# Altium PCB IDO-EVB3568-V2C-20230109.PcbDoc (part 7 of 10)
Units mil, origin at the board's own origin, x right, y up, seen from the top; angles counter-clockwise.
Board outline 5318 x 3544 mil, 2 copper layers (TOP, BOTTOM), stack 6.8 mil thick; 790 components, 626 nets, 2890 pads, 1922 vias.
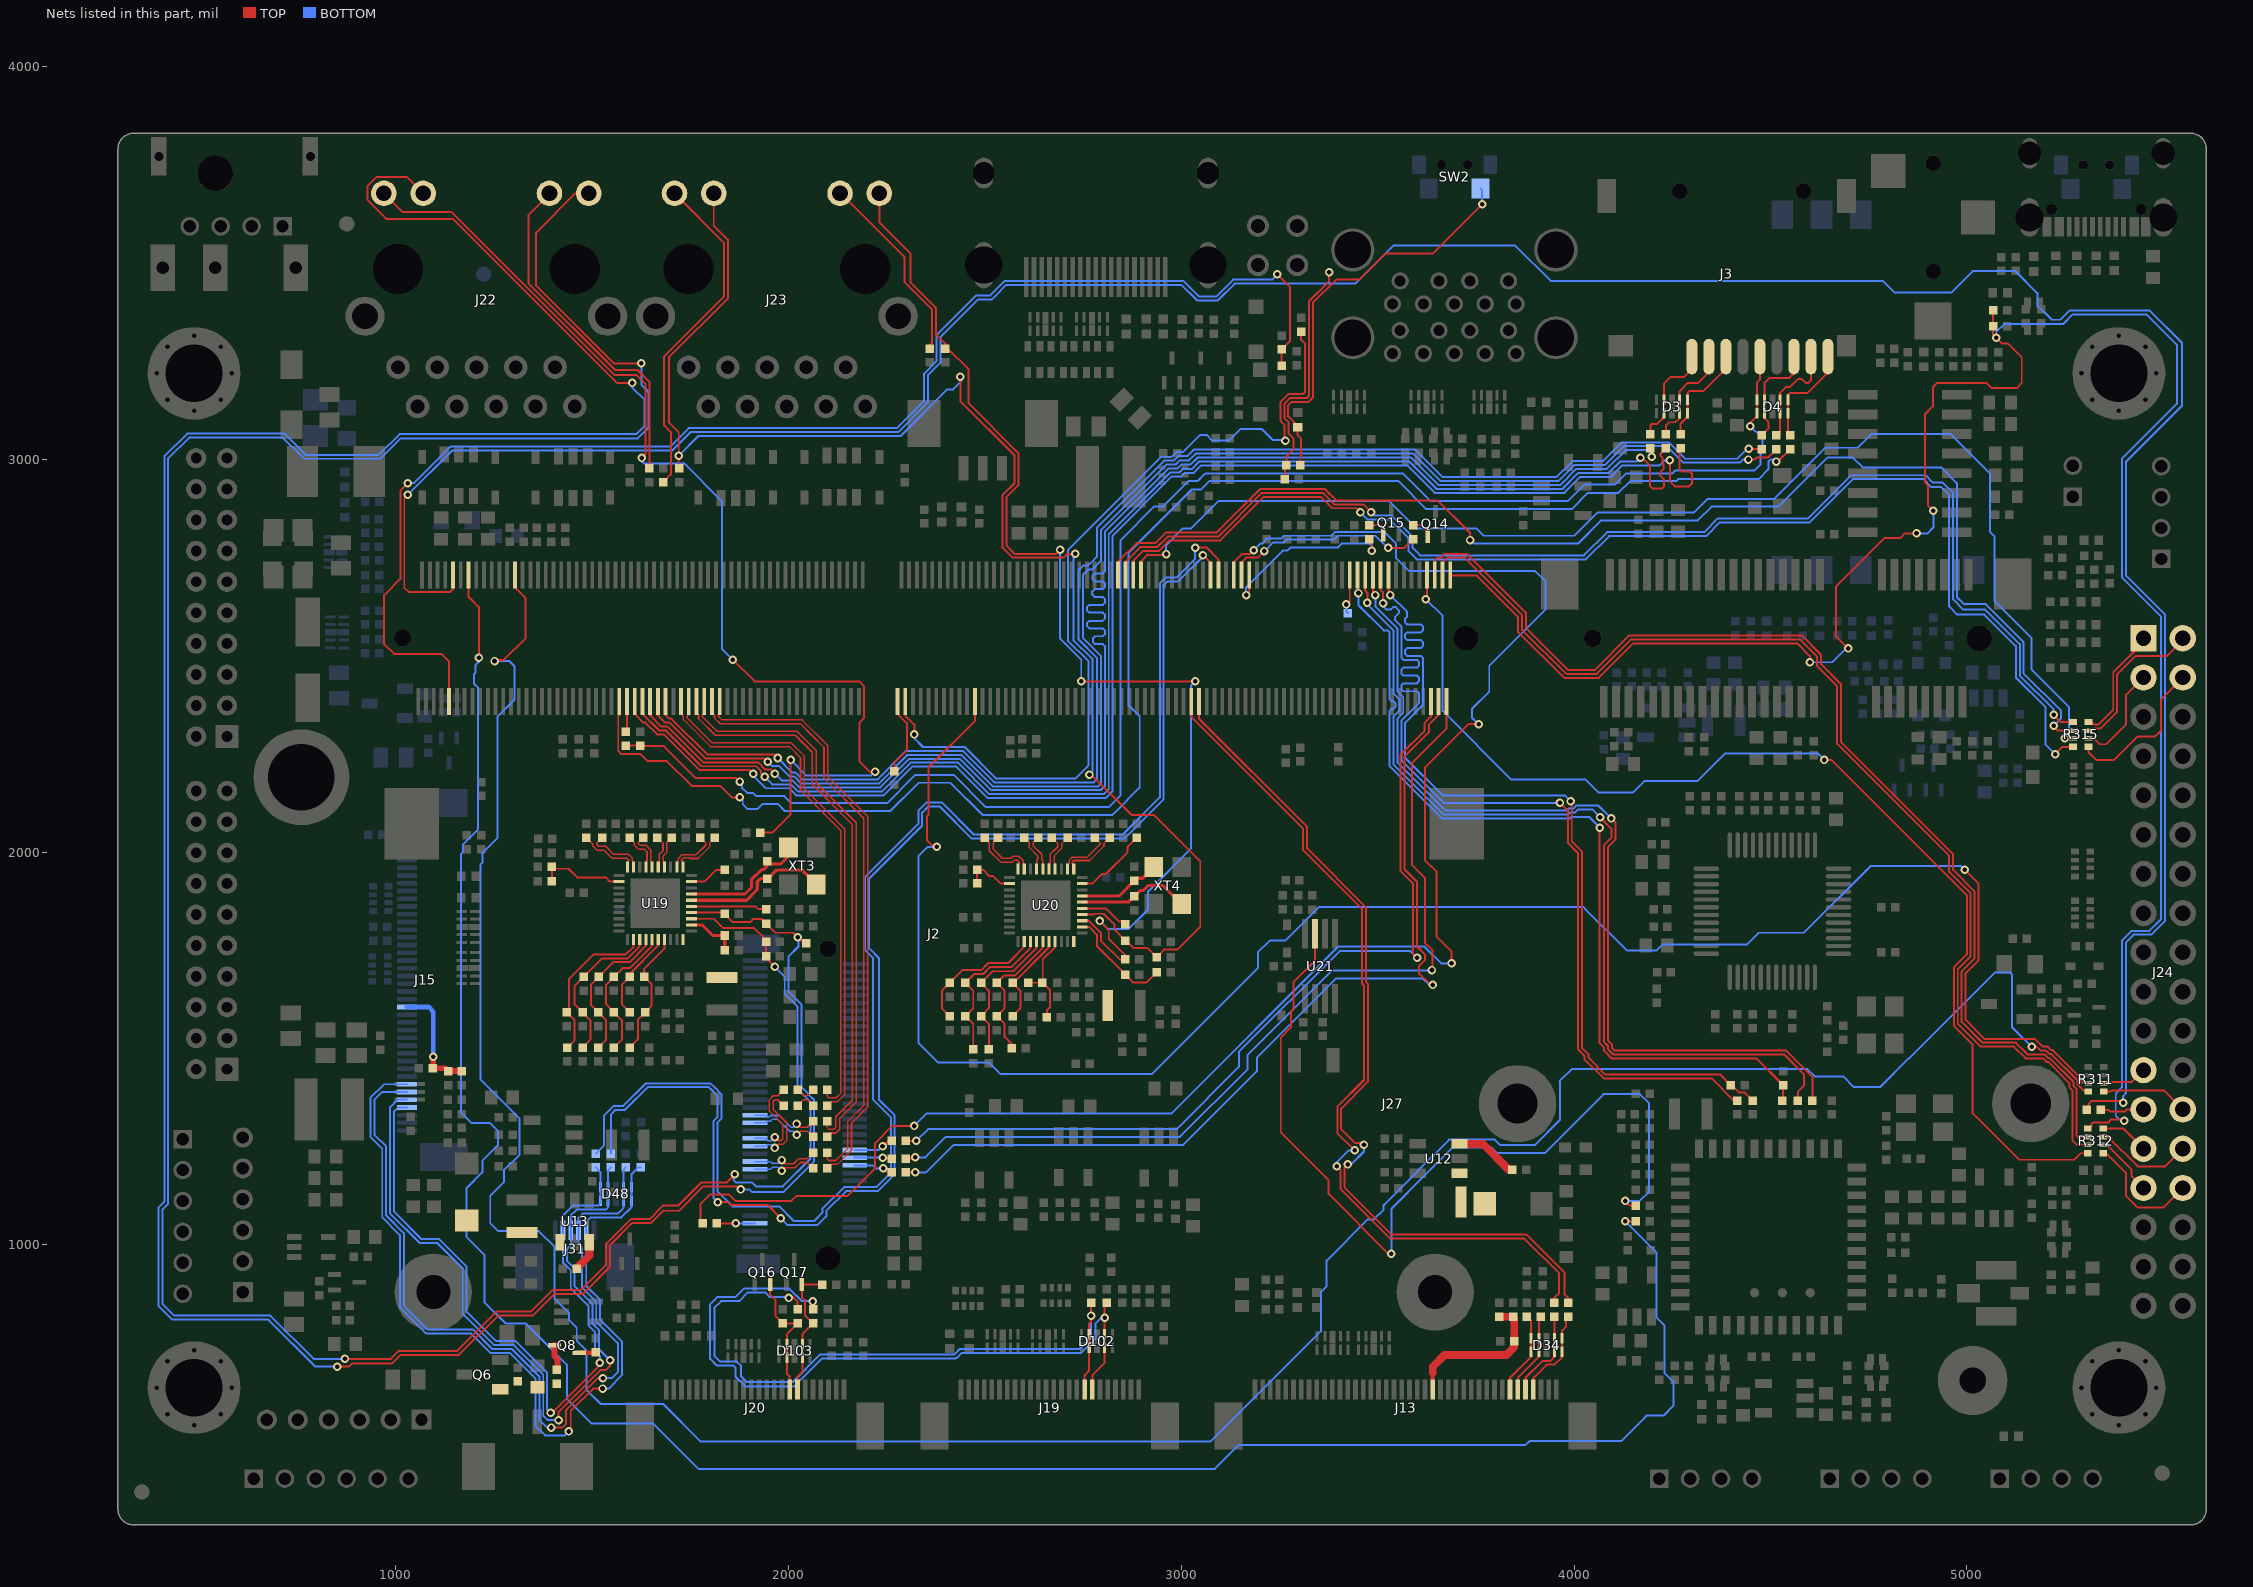
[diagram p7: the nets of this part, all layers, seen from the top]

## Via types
v1: diameter 21.65, hole 11.81, TOP to BOTTOM, 1878 vias
v2: diameter 17.72, hole 7.87, TOP to BOTTOM, 44 vias

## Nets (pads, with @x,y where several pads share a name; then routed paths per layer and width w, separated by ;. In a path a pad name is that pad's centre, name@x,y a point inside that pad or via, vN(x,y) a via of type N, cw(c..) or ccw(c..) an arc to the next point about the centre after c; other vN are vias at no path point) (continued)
N69911722: R99.2 U12.3 | length 161.6
  TOP w20: U12.3@3708.15,1257.4 3767.6,1257.4 3834,1191 R99.2@3842.28,1191
N69911786: C78.2 J13.17 R413.2 R415.2 | length 399.8
  TOP w10: J13.17@3639.96,632.01 3639.96,675
  TOP w20: 3639.96,675 3639.96,689.96 3670,720 3827.72,720 3847.72,740 C78.2@3847.72,755 3847.72,814.56 R413.2@3845,817.28 R415.2@3810,817.28
N69912226: D39.A L15.2 U12.1
N69922645: R117.2 U13.3 | length 80.4
  TOP w20: R117.2@1459.72,940 1492.4,972.68 U13.3@1492.4,1006.85
N69922778: D50.A L20.2 U13.1
N69927169: C92.1 Q6.1 R134.1 R136.1
N69927197: Q8.3 R136.2 | length 67.2
  TOP w15: Q8.3@1403.5,745 1403.5,716.5 1411,709 1411,683.72 R136.2@1409,681.72
N69927388: Q8.1 R137.1 | length 43.3
  TOP w12: Q8.1@1466.5,725.32 1507.04,725.32 R137.1@1509,727.28
N70033042: Q15.1 R89.2 | length 58.6
  TOP w5: R89.2@3478,2832.72 3509.32,2832.72 3514.32,2827.72 Q15.1@3514.32,2807.5
N70033056: Q14.1 R90.2 | length 56.1
  TOP w5: R90.2@3590,2832.72 3611.28,2832.72 3627.32,2816.68 Q14.1@3627.32,2804.5
N70059784: C258.2 J15.17 R408.2 R409.2 | length 293.9
  TOP w15: v1(1095,1479) 1095,1451.28 C258.2@1093.72,1450 1125.72,1450 R409.2@1133,1442.72 R408.2@1168,1442.72
  BOTTOM w12: J15.17@1027.99,1606.1 1083,1606.1 1095,1594.1 v1(1095,1479)
N70064377: D96.1 R412.2 SW2.3 | length 1056.2
  TOP w5: R412.2@3302.72,2985 3302.72,3004.33 3305,3006.61 3305,3053.38 3296,3062.38 D96.1@3296,3082.1 3296,3085.87 3272,3109.87 3272,3137.7 3281.3,3147 3324,3147 3335,3158 3335,3398.86 3395.14,3459 3454,3459 3520,3525 3640.95,3525 v1(3765.95,3650)
  BOTTOM w5: SW2.3@3761.95,3689.98 3765.95,3685.98 v1(3765.95,3650)
NTC_SARADC_VIN3: J2.5 R312.2 | length 2857.6
  TOP w5: J2.5@3645.27,2706.42 3645.27,2744 3650.27,2749 3660,2749 3671,2760 3727,2760 3877,2610 3877,2572 3985,2464 4053,2464 4141,2552 4579.25,2552 4629,2502.25 4629,2478.14 4680,2427.14 4680,2280.14 4965,1995.14 4965,1955 5020,1900 5020,1730 4987,1697 4987,1568 5040,1515 5125,1515 5155,1485 5198.09,1485 5207.16,1475.92 5211.02,1475.92 5271.97,1414.98 5271.97,1404.89 5278.92,1397.94 5278.92,1279.84 5283.92,1274.84 R312.2@5308.31,1274.84
PCIE20_CLKREQN_3V3_L: J27.52 R348.2 | length 95.3
  TOP w5: v1(2239.2,1222.2) 2241.41,1220 R348.2@2262.28,1220
  BOTTOM w5: J27.52@2167.91,1222.2 v1(2239.2,1222.2)
PCIE20_CLKREQN_M2_3V3_L: J2.2 R348.1 | length 2302.6
  TOP w5: R348.1@2297.72,1220 2319,1220 v1(2322,1223) ; v1(3638,1700) 3640,1702 3640,1750 3620,1770 3620,1935 3587.63,1967.37 3587.63,2227.63 3674.8,2314.8 J2.2@3674.8,2383.58
  BOTTOM w5: v1(2322,1223) 2348,1223 2400,1275 2412.14,1275 2445.28,1275.01 2467.86,1275 2996.29,1275 3168,1446.71 3168,1483 3384,1699 3637,1699 v1(3638,1700)
PCIE20_PERSTN_3V3_L: J27.50 R347.2 | length 103.9
  TOP w5: v1(2239,1250.89) 2253.11,1265 R347.2@2262.28,1265
  BOTTOM w5: J27.50@2167.91,1241.89 2230,1241.89 v1(2239,1250.89)
PCIE20_PERSTN_M2_3V3_L: J2.6 R347.1 | length 2234
  TOP w5: R347.1@2297.72,1265 v1(2325,1265) ; v1(3600,1731) 3590,1741 3590,1920 3557.63,1952.37 3557.63,2247.63 3618.5,2308.5 3618.5,2328.5 3635.43,2345.43 J2.6@3635.43,2383.58
  BOTTOM w5: v1(2325,1265) 2355,1295 2403.86,1295 2453.57,1295.01 ; 2453.57,1295 2476.14,1295 2988,1295 3146.5,1453.5 3146.5,1491.5 3403,1748 3583,1748 v1(3600,1731)
PCIE20_PRSNT_3V3_L: J27.69 R382.1 | length 97.3
  TOP w5: R382.1@1816.72,1055 1816.84,1054.88 v1(1865.12,1054.88)
  BOTTOM w5: v1(1865.12,1054.88) J27.69@1913.98,1054.88
PCIE20_PRSNT_3V3_L_GPIO3_A6: J2.57 R382.2 | length 4396
  TOP w5: R382.2@1781.28,1055 1780,1055 1775,1060 1775,1103.66 1800.34,1129 1847,1129 1864,1112 2007,1112 2020,1125 2150,1125 2220,1195 2220,1259.43 2263.57,1303 v1(2320,1303) ; J2.57@3133.46,2706.42 3133.46,2738.46 3155,2760 3175,2760 v1(3184,2769) ; v1(3688,1717) 3688,1747 3650,1785 3650,1950 3620,1980 3620,2215 3731,2326 v1(3757,2326)
  BOTTOM w5: v1(2320,1303) 2352,1335 2975,1335 3400,1760 3619,1760 3662,1717 v1(3688,1717) ; v1(3184,2769) 3201,2786 3206,2786 3219,2799 3254,2799 3261,2806 3382,2806 3392,2816 3517,2816 3547,2786 3547,2749 3580,2716 3901,2716 3927.33,2689.67 3927.33,2618.33 3784,2475 3784,2409 3740,2365 3740,2343 v1(3757,2326)
PCIE20_REFCLKN: J2.184 R360.1 | length 1517.3
  TOP w4: J2.184@1804.72,2383.58 1804.72,2355.28 1811,2349 1811,2342 1826,2327 2029.86,2327 2059.93,2296.93 2090,2266.86 2090,2187.86 2191,2086.86 2191,1355.14 2150,1314.14 2150,1245 2120,1215 2101.72,1215 2097.72,1219 R360.1@2097.72,1235
PCIE20_REFCLKN_: J27.53 R360.2 | length 169.3
  TOP w4: v1(1982,1216.16) 1991.16,1207 2012.86,1207 2025.86,1220 2047.28,1220 R360.2@2062.28,1235
  BOTTOM w4: J27.53@1913.98,1212.36 1953.47,1212.36 1958.31,1207.52 1973.35,1207.52 v1(1982,1216.16)
PCIE20_REFCLKP: J2.182 R361.1 | length 1519.2
  TOP w4: J2.182@1824.4,2383.58 1824.4,2353.84 1821,2350.44 1821,2346.14 1830.14,2337 2034,2337 2100,2271 2100,2192 2201,2091 2201,1351 2160,1310 2160,1240.86 2124.14,1205 2107.72,1205 R361.1@2097.72,1195
PCIE20_REFCLKP_: J27.55 R361.2 | length 168.9
  TOP w4: v1(1982,1188.87) 1990.13,1197 2017,1197 2030,1210 2047.28,1210 R361.2@2062.28,1195
  BOTTOM w4: J27.55@1913.98,1192.68 1953.47,1192.68 1958.31,1197.52 1973.36,1197.52 v1(1982,1188.87)
PCIE20_RXN: J2.188 R355.1 | length 1427.3
  TOP w4: J2.188@1765.35,2383.58 1765.35,2354.98 1770.33,2350 1770.33,2340.67 1813,2298 2016.86,2298 2059.93,2254.93 2059.93,2172.93 2162,2070.86 2162,1368.21 2120,1326.21 2120,1299 2116,1295 2101.72,1295 2097.72,1299 R355.1@2097.72,1315
PCIE20_RXN_: J27.41 R355.2 | length 178.2
  TOP w4: v1(2020,1308) 2028,1300 2047.28,1300 R355.2@2062.28,1315
  BOTTOM w4: J27.41@1913.98,1330.47 1939.53,1330.47 1945,1325 1948.86,1325 1953.49,1329.63 1976.37,1329.63 2006.67,1299.33 2011.33,1299.33 v1(2020,1308)
PCIE20_RXP: J2.186 R356.1 | length 1430.2
  TOP w4: J2.186@1785.03,2383.58 1785.03,2354.7 1780.33,2350 1780.33,2344.81 1817.14,2308 2021,2308 2069.93,2259.07 2069.93,2177.07 2172,2075 2172,1364.07 2130,1322.07 2130,1294.86 2120.14,1285 2107.72,1285 R356.1@2097.72,1275
PCIE20_RXP_: J27.43 R356.2 | length 178.4
  TOP w4: v1(2020.35,1280.35) 2030,1290 2047.28,1290 R356.2@2062.28,1275
  BOTTOM w4: J27.43@1913.98,1310.79 1940.79,1310.79 1945,1315 1953,1315 1957.63,1319.63 1972.23,1319.63 2002.53,1289.33 2011.38,1289.33 v1(2020.35,1280.35)
PCIE20_TX_N: C212.2 R357.1 | length 52
  TOP w4: R357.1@2022.72,1395 2037.72,1380 2047.28,1380 C212.2@2062.28,1395
PCIE20_TX_P: C213.2 R358.1 | length 52
  TOP w4: R358.1@2022.72,1355 2037.72,1370 2047.28,1370 C213.2@2062.28,1355
PCIE20_TXN: C212.1 J2.192 | length 1340.7
  TOP w4: J2.192@1725.98,2383.58 1725.98,2353.02 1732.01,2346.99 1732.01,2337.85 1800.86,2269 2001.86,2269 2030,2240.86 2030,2157.86 2133,2054.86 2133,1387.14 2120.86,1375 2101.72,1375 2097.72,1379 C212.1@2097.72,1395
PCIE20_TXN_: J27.47 R357.2 | length 242.9
  TOP w4: v1(1964.65,1274.22) 1972.87,1266 1981,1266 1985,1270 1985,1307 1951,1341 1951,1370.14 1960.86,1380 1972.28,1380 R357.2@1987.28,1395
  BOTTOM w4: J27.47@1913.98,1271.42 1940,1271.42 1945.84,1265.57 1956,1265.57 v1(1964.65,1274.22)
PCIE20_TXP: C213.1 J2.190 | length 1342.8
  TOP w4: J2.190@1745.66,2383.58 1745.66,2350.66 1742.01,2347.01 1742.01,2341.99 1805,2279 2006,2279 2040,2245 2040,2162 2143,2059 2143,1383 2125,1365 2107.72,1365 C213.1@2097.72,1355
PCIE20_TXP_: J27.49 R358.2 | length 242.4
  TOP w4: v1(1964.65,1246.93) 1973.72,1256 1985.14,1256 1995,1265.86 1995,1311.14 1961,1345.14 1961,1366 1965,1370 1972.28,1370 R358.2@1987.28,1355
  BOTTOM w4: J27.49@1913.98,1251.73 1940.16,1251.73 1944,1255.57 1956,1255.57 v1(1964.65,1246.93)
PCIE20_WAKEN_3V3_L: J27.54 R349.2 | length 101.6
  TOP w5: v1(2241,1195) 2251,1185 R349.2@2262.28,1185
  BOTTOM w5: J27.54@2167.91,1202.52 2214.15,1202.52 2221.67,1195 v1(2241,1195)
PCIE20_WAKEN_M2_3V3_L: J2.4 R349.1 | length 2377.6
  TOP w5: R349.1@2297.72,1185 v1(2322,1185) ; v1(3640,1662) 3635,1662 3605,1692 3605,1710 3620,1725 3620,1740 3600,1760 3600,1925 3567.63,1957.37 3567.63,2242.63 3630,2305 3630,2325 3655.11,2350.11 J2.4@3655.11,2383.58
  BOTTOM w5: v1(2322,1185) 2350,1185 2420,1255 2420.43,1255 2437,1255.01 2459.57,1255 2988,1255 3004.57,1255 3005,1255 3192,1442 3192,1477 3394,1679 3614,1679 3631,1662 v1(3640,1662)
PHY0_CLKOUT125: R216.2 U19.35 | length 192.7
  TOP w5: U19.35@1752.52,1862.13 1915,1862.13 1922.13,1855 R216.2@1942.28,1855
PHY0_G_LED-: J22.12 R213.1 | length 883.5
  TOP w5: J22.12@1390.8,3677.9 1390.8,3675.8 1337,3622 1337,3448.86 1557.86,3228 1615,3228 1645,3198 R213.1@1645,2977.72
PHY0_LED0/CFG_EXT: R225.2 R226.1 U19.32 | length 133.9
  TOP w8: U19.32@1752.52,1814.88 1780.12,1814.88 1807,1788 R225.2@1837.28,1788 R226.1@1837.28,1750
PHY0_LED1/CFG_LDO0: C133.2 J22.11 R233.2 U19.33 | length 7096.2
  TOP w5: v1(870,710) 987,710 1007,730 1155.86,730 1255.86,830 1343,830 1398,885 1470,885 1535,950 1535,994.86 1535,1003.14 1597.86,1066 1629.14,1066 1645.71,1066 1679.86,1100.14 1718.14,1100.14 1777,1159 1842,1159 v1(1863,1180) ; J22.11@1490.8,3677.9 1456.9,3677.9 1357,3578 1357,3443 1555,3245 v1(1625,3245) ; U19.33@1752.52,1830.63 1809.37,1830.63 1833,1807 1912,1807 1942.28,1776.72 C133.2@1942.28,1772 R233.2@1942.28,1735 1942.28,1730.72 v1(1965,1708)
  BOTTOM w5: v1(870,710) 790,710 680,820 435,820 405,850 405,1090 420,1105 420,3003 473,3056 712,3056 760.14,3007.86 766,3002 960.14,3002 1012.14,3054 1616,3054 1643,3081 1643,3172 1625,3190 v1(1625,3245) ; v1(1863,1180) 1860,1177 1860,1165 1865.41,1159.59 1906.16,1159.59 1916.75,1149 1985.14,1149 2055,1218.86 2055,1365 2023,1397 2023,1607 1990,1640 1990,1683 v1(1965,1708)
PHY0_LED2/CFG_LDO1: C132.2 J22.13 R229.2 R230.1 U19.34 | length 7598
  TOP w5: v1(850,690) 880,690 888.5,698.5 990.5,698.5 1012,720 1160,720 1260,820 1348,820 1403,875 1475,875 1545,945 1545,999 1602,1056 1625,1056 1649.85,1056 1680.93,1087.07 1721.07,1087.07 1783,1149 1868.08,1149 1875.82,1141.26 v1(1878,1141.26) ; J22.13@1069.2,3677.9 1027.1,3720 951,3720 927,3696 927,3661 975,3613 1144.57,3613 1562.57,3195 v1(1602,3195) ; U19.34@1752.52,1846.38 1833.9,1846.38 R229.2@1837.28,1843 1837.28,1842.72 1858,1822 1902,1822 1910,1830 1930.28,1830 C132.2@1942.28,1818 1965.28,1795 2011,1795 v1(2022.8,1783.2) 2038.28,1767.72 R230.1@2045,1767.72
  BOTTOM w5: v1(850,690) 795,690 675,810 430,810 395,845 395,1095 410,1110 410,3008 468,3066 716.14,3066 770.14,3012 956,3012 1009,3065 1612,3065 1633,3086 1633,3152 1602,3183 v1(1602,3195) ; v1(1878,1141.26) 1899.74,1141.26 1906,1135 1987,1135 2065,1213 2065,1369.14 2050,1384.14 2050,1385 2033,1402 2033,1612 2000,1645 2000,1735 2025,1760 2025,1781 v1(2022.8,1783.2)
PHY0_MDI0+: R223.1 U19.1 | length 136
  TOP w4: U19.1@1730.87,1962.52 1730.87,1974.13 1726.99,1978.01 1726.99,1980.83 1732.17,1986 1748,1986 1750,1984 1769,1984 1798.5,2013.5 1798.5,2023.78 R223.1@1812,2037.28
PHY0_MDI0-: R222.1 U19.2 | length 131.8
  TOP w4: U19.2@1715.12,1962.52 1715.12,1975.12 1718.99,1978.99 1718.99,1984.14 1728.85,1994 1764.86,1994 1788.5,2017.64 1788.5,2023.78 R222.1@1775,2037.28
PHY0_MDI1+: R221.1 U19.4 | length 84.8
  TOP w4: U19.4@1683.62,1962.52 1683.62,1974.38 1680.71,1977.29 1680.71,1990.71 1690,2000 1690,2025.28 R221.1@1702,2037.28
PHY0_MDI1-: R220.1 U19.5 | length 86
  TOP w4: R220.1@1665,2037.28 1680,2022.28 1680,2004.14 1670.71,1994.86 1670.71,1977.71 1667.87,1974.87 U19.5@1667.87,1962.52
PHY0_MDI2+: R425.1 U19.6 | length 103.4
  TOP w4: R425.1@1630,2037.28 1617.24,2024.52 1617.24,2021.9 1621.14,2018 1636.4,2018 1649.26,2005.14 1649.26,1977.74 1652.13,1974.87 U19.6@1652.13,1962.52
PHY0_MDI2-: R424.1 U19.7 | length 103.2
  TOP w4: R424.1@1595,2037.28 1607.24,2025.04 1607.24,2017.76 1617,2008 1632.26,2008 1639.26,2001 1639.26,1978.26 1636.38,1975.38 U19.7@1636.38,1962.52
PHY0_MDI3+: R215.1 U19.9 | length 152.3
  TOP w4: R215.1@1525,2037.28 1511,2023.28 1511,2020.14 1516.14,2015 1534,2015 1554,1995 1592.15,1995 1602.01,1985.14 1602.01,1977.88 1604.88,1975 U19.9@1604.88,1962.52
PHY0_MDI3-: R214.1 U19.10 | length 153.1
  TOP w4: R214.1@1485,2037.28 1501,2021.28 1501,2016 1512,2005 1529.86,2005 1549.86,1985 1588.01,1985 1592.01,1981 1592.01,1977.01 1589.13,1974.13 U19.10@1589.13,1962.52
PHY0_REG_OUT: L22.1 U19.30
PHY0_RSTN: C143.2 R248.2 U19.12 | length 223.5
  TOP w5: R248.2@1396.72,1926 C143.2@1396.72,1963 1401.72,1958 1439.28,1958 1461.28,1936 1534,1936 1544.88,1925.12 U19.12@1567.48,1925.12
PHY0_RXCLK/PHYAD1: R237.2 R238.1 R256.1 U19.27 | length 327.4
  TOP w5: R238.1@1595,1502.72 1616,1523.72 1616,1573.72 R256.1@1635,1592.72 1651,1608.72 1651,1664 1632.28,1682.72 R237.2@1632,1682.72 1632,1703 1683.62,1754.62 U19.27@1683.62,1777.48
PHY0_RXD0/RXDLY: R239.2 R240.1 R252.1 U19.25 | length 358.5
  TOP w5: R240.1@1555,1502.72 1575,1522.72 1575,1572.72 R252.1@1555,1592.72 1535,1612.72 1535,1662.72 R239.2@1555,1682.72 1577.28,1705 1595,1705 1652.13,1762.13 U19.25@1652.13,1777.48
PHY0_RXD1/TXDLY: R242.2 R243.1 R253.1 U19.24 | length 381
  TOP w5: R243.1@1515,1502.72 1535,1522.72 1535,1572.72 R253.1@1515,1592.72 1497,1610.72 1497,1663.72 R242.2@1516,1682.72 1553.28,1720 1595,1720 1636.38,1761.38 U19.24@1636.38,1777.48
PHY0_RXD2/PLLOFF: R245.2 R246.1 R254.1 U19.23 | length 406.1
  TOP w5: R246.1@1475,1502.72 1495,1522.72 1495,1572.72 R254.1@1475,1592.72 1455,1612.72 1455,1659.72 R245.2@1478,1682.72 1525.28,1730 1590,1730 1620.63,1760.63 U19.23@1620.63,1777.48
PHY0_RXD3/PHYAD0: R236.1 R255.1 U19.22 | length 409.3
  TOP w5: R236.1@1436,1502.72 1455,1521.72 1455,1572.72 R255.1@1435,1592.72 1440,1597.72 1440,1677 1503,1740 1585,1740 1604.88,1759.88 U19.22@1604.88,1777.48
PHY0_RXDV/PHYAD2: R235.2 R257.1 U19.26 | length 231.5
  TOP w5: R257.1@1595,1592.72 1575,1612.72 1575,1662.72 R235.2@1595,1682.72 1595,1690 1667.87,1762.87 U19.26@1667.87,1777.48
PHY0_XTALIN: C130.2 U19.36 XT3.3 | length 376.8
  TOP w8: U19.36@1752.52,1877.87 1892.87,1877.87 1920,1905 1920,1924.72 1928,1932.72 C130.2@1945,1932.72 1947.72,1932.72 1970,1955 2033.19,1955 XT3.3@2070.43,1917.76
PHY0_XTALOUT: C129.2 U19.37 XT3.1 | length 334.4
  TOP w8: U19.37@1752.52,1893.62 1888.62,1893.62 1905,1910 1905,1930 1931.14,1956.14 1936.14,1956.14 1945,1965 C129.2@1945,1977.28 1947.72,1977.28 1955,1970 1980,1970 1999.57,1989.57 XT3.1@1999.57,2012.24
PHY0_Y_LED+: J22.14 R211.1 | length 2811.2
  TOP w5: J22.14@969.2,3677.9 1017.1,3630 1141.71,3630 1556.71,3215 1613,3215 1635,3193 1635,3013 v1(1626,3004) ; v1(1857.5,2490.5) 1913,2435 2180,2435 2192,2423 2192,2342 2180,2330 2180,2231.14 2207.82,2203.33 2217.83,2203.33 v1(2219.92,2205.41) ; R211.1@1927.72,2050 1958,2050 2005,2097 v1(2005,2235)
  BOTTOM w5: v1(1626,3004) 1626,2995 1631,2990 1734,2990 1830,2894 1830,2518 v1(1857.5,2490.5) ; v1(2005,2235) 2045,2195 2209.51,2195 v1(2219.92,2205.41)
PHY1_CLKOUT125: R270.2 U20.35 | length 126.4
  TOP w5: U20.35@2747.52,1857.13 2807.87,1857.13 2841,1824 2850.28,1824 R270.2@2857.28,1817
PHY1_G_LED-: J23.12 R268.1 | length 495.4
  TOP w5: J23.12@2130.8,3677.9 2132.1,3677.9 2295,3515 2295,3452 2365,3382 2365,3298 2359,3292 R268.1@2359,3282.72
PHY1_LED0/CFG_EXT: R273.2 R274.1 U20.32 | length 277.1
  TOP w5: U20.32@2747.52,1809.88 2765.12,1809.88 2785,1790 2785,1761.28 2857.28,1689 R273.2@2857.28,1688 2877.28,1668 2910.28,1668 R274.1@2937.28,1695
PHY1_LED1/CFG_LDO0: C157.2 J23.11 R281.2 U20.33 | length 2926.2
  TOP w5: J23.11@2230.8,3677.9 2230.8,3604.2 2310,3525 2310,3451.14 2375,3386.14 2375,3319 2399,3295 C157.2@2399,3282.72 2405.28,3282.72 2458,3230 2458,3143 2585,3016 2585,2935 2555,2905 2555,2780 2575,2760 2681,2760 v1(2691,2770) ; v1(2745,2435) v1(3035,2435) ; U20.33@2747.52,1825.63 2764.37,1825.63 2795,1795 2795,1775 2843,1727 R281.2@2857.28,1727 2857.28,1737.72 2815,1780 2815,1802 v1(2792,1825)
  BOTTOM w5: v1(2691,2770) 2691,2544 2745,2490 v1(2745,2435) ; v1(2792,1825) 2812,1805 2866,1805 2915,1854 2915,1900 3025,2010 3025,2425 v1(3035,2435)
PHY1_LED2/CFG_LDO1: C156.2 J23.13 R277.2 R278.1 U20.34 | length 3817.6
  TOP w5: C156.2@1721,2977.72 1720,2978.72 v1(1720,3010) 1720,3070 1695,3095 1695,3260 1845,3410 1845,3560 1809.2,3595.8 J23.13@1809.2,3677.9 ; v1(2437.28,3211) 2437.28,3148.72 2575,3011 2575,2940 2545,2910 2545,2775 2570,2750 2700,2750 2710,2760 v1(2730,2760) ; U20.34@2747.52,1841.38 2776.38,1841.38 2778.38,1843.38 2801.62,1843.38 2830,1815 2830,1802.28 R277.2@2857.28,1775 2860,1775 2879,1756 2914.28,1756 R278.1@2937.28,1733 2956.28,1752 2990,1752 3048,1810 3048,1977 2930,2095 2873,2095 2771,2197 v1(2766,2197)
  BOTTOM w5: v1(1720,3010) 1770,3060 2266.71,3060 2283.28,3060 2285,3060 2403,3178 2418,3178 2438.46,3198.46 2438.46,3205.54 2437.28,3206.72 v1(2437.28,3211) ; v1(2730,2760) 2725,2755 2725,2540 2774,2491 2774,2205 v1(2766,2197)
PHY1_MDI0+: R266.1 U20.1 | length 144.6
  TOP w4: U20.1@2725.87,1957.52 2725.87,1968.12 2721.99,1972 2721.99,1975.68 2725.31,1979 2766,1979 2803,2016 2803,2023.28 R266.1@2817,2037.28
PHY1_MDI0-: R265.1 U20.2 | length 141.7
  TOP w4: U20.2@2710.12,1957.52 2710.12,1968 2713.99,1971.88 2713.99,1978.99 2722,1987 2759.86,1987 2793,2020.14 2793,2024.28 R265.1@2780,2037.28
PHY1_MDI1+: R264.1 U20.4 | length 95.2
  TOP w4: U20.4@2678.62,1957.52 2678.62,1971.38 2675.71,1974.29 2675.71,1990.71 2695,2010 2695,2022.28 R264.1@2710,2037.28
PHY1_MDI1-: R263.1 U20.5 | length 95.1
  TOP w4: U20.5@2662.87,1957.52 2662.87,1971.87 2665.71,1974.71 2665.71,1994.86 2685,2014.14 2685,2022.28 R263.1@2670,2037.28
PHY1_MDI2+: R262.1 U20.6 | length 94.7
  TOP w4: R262.1@2635,2037.28 2623,2025.28 2623,2016.14 2644.26,1994.89 2644.26,1982.13 2647.13,1979.25 U20.6@2647.13,1957.52
PHY1_MDI2-: R261.1 U20.7 | length 95.1
  TOP w4: R261.1@2600,2037.28 2613,2024.28 2613,2012 2634.26,1990.74 2634.26,1982.13 2631.38,1979.25 U20.7@2631.38,1957.52
PHY1_MDI3+: R260.1 U20.9 | length 149
  TOP w4: R260.1@2533,2037.28 2521,2025.28 2521,2008.14 2544.14,1985 2565.86,1985 2570.86,1990 2586,1990 2597.01,1978.99 2597.01,1971.99 2599.88,1969.12 U20.9@2599.88,1957.52
PHY1_MDI3-: R259.1 U20.10 | length 149
  TOP w4: R259.1@2499,2037.28 2511,2025.28 2511,2004 2540,1975 2570,1975 2575,1980 2581.86,1980 2587.01,1974.85 2587.01,1972.01 2584.13,1969.13 U20.10@2584.13,1957.52
PHY1_REG_OUT: L23.1 U20.30
PHY1_RSTN: C167.2 R296.2 U20.12 | length 131.2
  TOP w5: R296.2@2479.72,1921 C167.2@2479.72,1955 2495,1955 2510,1940 2520,1940 2539.88,1920.12 U20.12@2562.48,1920.12
PHY1_RXCLK/PHYAD1: R284.2 R285.1 R304.1 U20.27 | length 253.2
  TOP w5: R304.1@2610,1667.72 R284.2@2646,1667.72 R284.2@2647,1667.72 ; R285.1@2657.28,1580 2657.28,1597.28 2665,1605 2665,1649.72 R284.2@2647,1667.72 ; U20.27@2678.62,1772.48 2678.62,1758.62 2647,1727 R284.2@2647,1667.72
PHY1_RXD0/RXDLY: R287.2 R288.1 R300.1 U20.25 | length 368.7
  TOP w5: R287.2@2568.28,1501 2568.28,1511.72 2550,1530 2550,1562.72 R288.1@2530,1582.72 2550,1602.72 2550,1647.72 R300.1@2530,1667.72 2548.28,1686 2556.02,1686 2556.07,1686.05 2576.05,1686.05 2647.13,1757.13 U20.25@2647.13,1772.48
PHY1_RXD1/TXDLY: R290.2 R291.1 R301.1 U20.24 | length 389.1
  TOP w5: R291.1@2510,1497.72 2510,1562.72 R290.2@2490,1582.72 2510,1602.72 2510,1647.72 R301.1@2490,1667.72 2519.28,1697 2572,1697 2631.38,1756.38 U20.24@2631.38,1772.48
PHY1_RXD2/PLLOFF: R293.2 R294.1 R302.1 U20.23 | length 413.7
  TOP w5: R294.1@2470,1497.72 2470,1562.72 R293.2@2450,1582.72 2470,1602.72 2470,1647.72 R302.1@2450,1667.72 2472.28,1690 2495,1690 2513,1708 2568,1708 2615.63,1755.63 U20.23@2615.63,1772.48
PHY1_RXD3/PHYAD0: R283.1 R303.1 U20.22 | length 342.8
  TOP w5: R283.1@2410,1582.72 2390,1602.72 2390,1647.72 R303.1@2410,1667.72 2442.28,1700 2490,1700 2508,1718 2559,1718 2599.88,1758.88 U20.22@2599.88,1772.48
PHY1_RXDV/PHYAD2: R286.2 R305.1 U20.26 | length 246.4
  TOP w5: R305.1@2570,1582.72 2590,1602.72 2590,1647.72 R286.2@2570,1667.72 2572.72,1667.72 2662.87,1757.87 U20.26@2662.87,1772.48
PHY1_XTALIN: C153.2 U20.36 XT4.3 | length 289.9
  TOP w8: U20.36@2747.52,1872.87 2865.15,1872.87 C153.2@2880,1887.72 2894.78,1902.5 2902.5,1902.5 2915,1915 2953.19,1915 XT4.3@3000.43,1867.76
PHY1_XTALOUT: C154.2 U20.37 XT4.1 | length 212.5
  TOP w8: U20.37@2747.52,1888.62 2841.34,1888.62 C154.2@2880,1927.28 2886.56,1933.84 2901.16,1933.84 XT4.1@2929.57,1962.24
PHY1_Y_LED+: J23.14 R267.1 | length 866
  TOP w5: R267.1@1680,2942.28 1700,2962.28 1700,3070 1683,3087 1683,3263 1835,3415 1835,3552.1 J23.14@1709.2,3677.9
PWM3_IR: J2.124 R311.3 | length 4796.8
  TOP w5: v1(2376.89,2013.89) 2374.11,2013.89 2374,2014 2368,2014 2351.67,2030.33 2351.67,2091.59 2356,2095.92 2356,2216 2474.01,2334.01 J2.124@2474.01,2383.58 ; v1(4995,1955) 5030,1920 5030,1725 4997,1692 4997,1573 5045,1525 5173,1525 5193,1505 5206.37,1505 5215.45,1495.92 5219.31,1495.92 5291.97,1423.27 5291.97,1417.19 5297,1412.16 R311.3@5309.31,1412.16
  BOTTOM w5: v1(2376.89,2013.89) 2353.89,2013.89 2330,1990 2330,1515 2380,1465 2510,1465 2540,1435 2925,1435 3195,1705 3195,1745 3225,1775 3265,1775 3350,1860 4024.14,1860 4030,1854.14 4134.14,1750 4210,1750 4225,1765 4440,1765 4470,1795 4585,1795 4755,1965 4985,1965 v1(4995,1955)
PWM3_IR_: J24.23 R311.6 | length 114.9
  TOP w5: R311.6@5348.69,1412.16 5367.03,1412.16 5370.03,1415.16 5420.16,1415.16 J24.23@5450,1445
PWM13_M1: J2.144 R110.1 | length 200
  TOP w5: R110.1@2269,2206.72 2269,2228 2301,2260 2301,2329 2278.16,2351.84 2278.16,2382.58 J2.144@2277.16,2383.58
PWRON: J24.25 R314.2 | length 113
  TOP w5: R314.2@5340.72,1344 5360.05,1344 5364.05,1340 5403.03,1340 5408.03,1345 J24.25@5450,1345
RESET: J24.26 R311.5 | length 222.6
  TOP w5: R311.5@5348.69,1390.5 5367.03,1390.5 5370.03,1393.5 5501.5,1393.5 J24.26@5550,1345
RK809-CLK32K: J2.247 R205.1 | length 5880.6
  TOP w5: J2.247@1184.64,2706.42 1184.64,2650.36 1211,2624 1211,2507 1214,2504 1214,2498.26 v1(1211.35,2495.61) ; v1(4130,1060) R205.1@4157.28,1060
  BOTTOM w5: v1(1211.35,2495.61) 1211.35,2485.35 1202,2476 1202,2456.48 1198.67,2453.15 1198.67,2437.14 1198.67,2428.85 1209,2418.52 1209,2058 1170.5,2019.5 1170.5,2000.5 1165,1995 1165,1337.67 1192,1310.67 1239.33,1310.67 1260,1290 1260,1255 1220,1215 1220,1185 1180,1145 1180,1020 1225,975 1225,854 1279,800 1330,800 1435,695 1435,608.43 1498.43,545 1655,545 1770,430 3085,430 3145,490 3876,490 3886.5,500.5 4106.21,500.5 4106.71,501 4120.85,501 4167.96,548.1 4185.53,565.67 4227.74,565.67 4253,590.94 4253,652 4230,675 4230,795 4210,815 4210,980 v1(4130,1060)
RK809_PWRON: C259.2 J2.251 R314.1 R412.1 | length 8349.8
  TOP w5: v1(1030,2910) 1021,2901 1021,2674 1032,2663 1138.27,2663 1145.27,2670 J2.251@1145.27,2706.42 ; C259.2@3263.28,2950 3263.28,2981 R412.1@3267.28,2985 3267.28,3007.28 3285,3025 3285,3054 3273,3066 3273,3094.72 3262,3105.72 3262,3141.85 3277.15,3157 3319.86,3157 3325,3162.14 3325,3403 3376,3454 v1(3376,3477) ; R314.1@5305.28,1344 5305.28,1344.89 5309.39,1349 5309.39,1357.93 5318.46,1367 5393,1367 v1(5398,1362)
  BOTTOM w5: v1(1030,2910) 1143,3023 1703,3023 1750,3070 2270.86,3070 2279.14,3070 2354.67,3145.53 2354.67,3214.74 2386,3246.06 2386,3311.86 2482.14,3408 2517.57,3408 2523.43,3413.86 2554.57,3445 2616.14,3445 3000,3445 3040,3405 3092.71,3405 3135.71,3448 3376,3448 ; v1(3376,3477) 3376,3448 ; v1(5398,1362) 5398,1379 5405,1386 5405,1770 5425,1790 5470,1790 5505,1825 5505,2605 5406,2704 5406,2995 5548,3137 5548,3297 5465,3380 5262,3380 5238,3356 5217,3356 5180,3393 5180,3424 5124,3480 5015,3480 4960,3425 4816,3425 4786,3455 3940,3455 3850,3545 3540,3545 3443,3448 3376,3448
RK809_VDC: J2.252 R7.1 R9.2 | length 3522.8
  TOP w5: v1(1030,2940) 1011,2921 1011,2696 970,2655 970,2530 995,2505 1115,2505 1135.43,2484.57 J2.252@1135.43,2383.58 ; v1(3244,3472) 3276.33,3439.67 3276.33,3301.61 R9.2@3255,3280.28 R7.1@3255,3238.72
  BOTTOM w5: v1(1030,2940) 1045,2940 1134,3029 1134.86,3029 1138.86,3033 1698,3033 1745,3080 2275,3080 2344.67,3149.67 2344.67,3218.88 2376,3250.21 2376,3316 2478,3418 2513.43,3418 2550.43,3455 2683.57,3455 3005,3455 3045,3415 3088.57,3415 3131.57,3458 3231,3458 3244,3471 v1(3244,3472)
RSET0: R241.2 U19.39 | length 97.1
  TOP w5: U19.39@1752.52,1925.12 1785.12,1925.12 1815,1955 R241.2@1837.28,1955
RSET1: R289.2 U20.39 | length 195.4
  TOP w5: U20.39@2747.52,1920.12 2773.12,1920.12 2798,1945 2808,1945 2863,2000 2863,2014.28 R289.2@2886,2037.28
RTCIC_32KOUT: R206.1 U21.7 | length 2212.4
  TOP w5: U21.7@3340.2,1792.68 3340.2,1724.2 3285,1669 3285,1600 3279,1594 3279,1554 3253,1528 3253,1287 3375,1165 3375,1130 3527,978 v1(3534,978) ; v1(4130,1112) 4142,1100 R206.1@4157.28,1100
  BOTTOM w5: v1(3534,978) 3535.14,979.14 3535.14,1092.86 3620.67,1178.39 3620.67,1178.95 3646.05,1204.32 3646.61,1204.32 3690.29,1248 3789.81,1248 3803.74,1234.07 3812.02,1234.07 3820.3,1234.07 ; 3820.31,1234.08 3925.18,1234.08 4075.1,1384 4167.49,1384 4191,1360.49 4191,1136 4167,1112 v1(4130,1112)
SARADC_VIN0_: J24.27 R312.8 | length 123.6
  TOP w5: R312.8@5347.69,1296.5 5398.5,1296.5 J24.27@5450,1245
SARADC_VIN0_KEY/RECOVERY: C182.2 J2.1 R312.1 R330.1 | length 5341.8
  TOP w5: J2.1@3684.64,2706.42 3686.64,2704.42 3752.58,2704.42 3857,2600 3857,2562 3975,2444 4063,2444 4151,2532 4568,2532 4600.67,2499.33 v1(4600.67,2483.83) ; v1(4698,2519) 4697,2519 4667,2549 4667,2677 4790,2800 4830,2800 4842,2812 v1(4872,2812) ; v1(4915,2870) 4901,2884 4901,2934 4894,2941 4894,3116 4913.5,3135.5 4913.5,3183.5 4925,3195 5050,3195 5063,3182 5127,3182 5140,3195 5140,3260 5104,3296 5089,3296 v1(5075,3310) 5067.28,3317.72 C182.2@5067.28,3340 R330.1@5067.28,3380 ; R312.1@5308.31,1296.5 5312.34,1296.5 5317.34,1301.5 5317.34,1307.45 5321.73,1311.85 5359.85,1311.85 5368,1320 5397,1320 v1(5401,1316)
  BOTTOM w5: v1(4600.67,2483.83) 4657.83,2483.83 4693,2519 v1(4698,2519) ; v1(4872,2812) 4900,2812 4915,2827 v1(4915,2870) ; v1(5075,3310) 5075,3325 5095,3345 5245,3345 5269,3369 5458,3369 5535,3292 5535,3142 5395,3002 5395,2700 5495,2600 5495,1830 5465,1800 5420,1800 5395,1775 5395,1401 5379.33,1385.33 5379.33,1328.67 5388,1320 5397,1320 v1(5401,1316)
SARADC_VIN2_: J24.29 R312.6 | length 157.9
  TOP w5: R312.6@5347.69,1255.16 5356.84,1255.16 5420,1192 5420,1175 J24.29@5450,1145
SARADC_VIN2_HP_HOOK: J2.3 R312.3 | length 2840.3
  TOP w5: J2.3@3664.96,2706.42 3664.96,2737.96 3677,2750 3722,2750 3867,2605 3867,2567 3980,2454 4058,2454 4146,2542 4575.11,2542 4619,2498.11 4619,2474 4670,2423 4670,2276 4955,1991 4955,1950 5010,1895 5010,1735 4977,1702 4977,1563 5035,1505 5120,1505 5150,1475 5193.94,1475 5203.02,1465.92 5206.88,1465.92 5261.97,1410.84 5261.97,1400.75 5268.92,1393.8 5268.92,1266.08 5279.84,1255.16 R312.3@5308.31,1255.16
SARADC_VIN3_: J24.28 R312.7 | length 252
  TOP w5: R312.7@5347.69,1274.84 5360.16,1274.84 5435,1200 5505,1200 J24.28@5550,1245
SARADC_VIN4: J2.7 R312.4 | length 2915.3
  TOP w5: v1(3622.59,2644.59) 3625.59,2647.59 J2.7@3625.59,2706.42 ; v1(4637,2235) 4655,2235 5000,1890 5000,1740 4967,1707 4967,1558 5015,1510 5015,1335 5133,1217 5273.46,1217 5289.97,1233.5 R312.4@5308.31,1233.5
  BOTTOM w5: v1(3622.59,2644.59) 3665,2602.18 3665,2360 3840,2185 4021,2185 4029.28,2185 4062.29,2152 4149.86,2152 4178.86,2181 4187.14,2181 4313.86,2181 4384.86,2252 4620,2252 v1(4637,2235)
SARADC_VIN4_: J24.30 R312.5 | length 315
  TOP w5: R312.5@5347.69,1233.5 5355.49,1233.5 5405,1184 5405,1125 5435,1095 5500,1095 J24.30@5550,1145
SCL_CAM0: D102.2 D102.9 J19.7 R152.2 R159.1 | length 1828.6
  TOP w5: v1(2061,856) 2061,836.72 R159.1@2062,835.72 ; J19.7@2773.27,632.01 2773.27,668.27 2804.68,699.68 D102.9@2804.68,737.78 D102.2@2804.68,772.22 v1(2804.68,815) 2804.68,846.96 R152.2@2810,852.28
  BOTTOM w5: v1(2061,856) 2060,857 2033.86,857 2001.86,889 1886,889 1864,867 1818,867 1800,849 1800,710 1817,693 1859,693 1864,688 1864,665 1889,640 2014,640 2084.5,710.5 2424.32,710.5 2425.82,712 2427.14,712 2428.14,713 2429,713 2441,725 2745,725 2781,761 2781,799 2797.3,815.3 2804.38,815.3 v1(2804.68,815)
SCL_CAM1: D103.2 D103.9 J20.7 Q17.2 R159.2 R162.1 | length 347.4
  TOP w5: J20.7@2022.56,632.01 2023,632.45 2023,665 2034.68,676.68 D103.9@2034.68,712.78 D103.2@2034.68,747.22 2034.68,772.96 R159.2@2062,800.28 2042,820.28 2042,859 2033.68,867.32 Q17.2@2033.68,899.5 2034.19,899 R162.1@2085.28,899
SDA_CAM0: D102.4 D102.7 J19.8 R153.2 R160.1 | length 1712.9
  TOP w5: v1(1999.97,864.97) 2001.96,866.96 2011.04,866.96 2023,855 R160.1@2023,835.72 ; J19.8@2753.58,632.01 2753.58,668.58 2765.32,680.32 D102.7@2765.32,737.78 D102.4@2765.32,772.22 2765.32,800.32 2770,805 v1(2770,820) R153.2@2770,852.28
  BOTTOM w5: v1(1999.97,864.97) 1997.94,867 1952,867 1940,879 1896,879 1874,857 1828,857 1811,840 1811,718 1826,703 1868,703 1879,692 1879,665 1893,651 2010,651 2079.5,720.5 2420.18,720.5 2421.68,722 2423,722 2436,735 2740,735 2770,765 v1(2770,820)
SDA_CAM1: D103.4 D103.7 J20.8 Q16.2 R160.2 R161.1 | length 333.5
  TOP w5: Q16.2@1952.68,899.5 1952.68,873.32 1966,860 1966,819.28 R161.1@1985,800.28 R160.2@2023,800.28 1995.32,772.6 D103.4@1995.32,747.22 D103.7@1995.32,712.78 1995.32,672.68 2002,666 2002,632.88 J20.8@2002.88,632.01
SDMMC0_CLK: J2.206 R21.1 | length 78.2
  TOP w5: R21.1@1585,2306.72 1588.18,2309.9 J2.206@1588.18,2383.58
SDMMC0_CLK_: C30.2 D4.1 D4.10 J3.5 R21.2 | length 4120.8
  TOP w5: R21.2@1585,2271.28 C30.2@1622,2271.28 1623.28,2270 1682,2270 1763,2189 1866,2189 v1(1875,2180) ; v1(4449,3085) 4449,3094 4465.63,3110.63 D4.1@4465.63,3117.78 D4.10@4465.63,3152.22 4465.63,3195.63 4473.23,3203.23 J3.5@4473.23,3262.13
  BOTTOM w5: v1(1875,2180) 1881.44,2173.56 1881.44,2163.56 1894,2151 1909,2151 1917,2143 1989,2143 2007,2125 2250.86,2125 2322.87,2197.01 2339.44,2197.01 2351.86,2197.01 2364.29,2197.01 2372.57,2197 2419.86,2197 2501.86,2115 2815,2115 2845,2145 2845,2795 2931,2881 2954,2881 3018,2945 3041,2945 3058,2962 3058.86,2962 3061.86,2965 3564,2965 3635,2894 3984,2894 4026,2936 4104,2936 4133,2965 4250.86,2965 4255.53,2969.67 4255.74,2969.67 4258.06,2972 4431.94,2972 4432.26,2971.67 4455.74,2971.67 4456.06,2972 4458.14,2972 4459.14,2973 4460,2973 4475,2988 4475,3015 4480,3020 4480,3054 v1(4449,3085)
SDMMC0_CMD: J2.204 R20.1 | length 3849.8
  TOP w5: J2.204@1607.87,2383.58 1607.87,2352.13 1630,2330 1635,2330 1665,2300 1682,2300 1773,2209 1901,2209 v1(1910,2200) ; v1(4244,2998) 4244,2945 4258,2931 4292,2931 4300,2939 4300,2964 4295,2969 4274,2969 4268,2975 4268,3026.28 R20.1@4271,3029.28
  BOTTOM w5: v1(1910,2200) 1910,2195 1942,2163 2001.14,2163 2019.14,2145 2242,2145 2315,2218 2427.14,2218 2507.14,2138 2807,2138 2825,2156 2825,2806 2976,2957 3000,2957 3009,2966 3032,2966 3051,2985 3575,2985 3645,2915 3975,2915 4016,2956 4094,2956 4123,2985 4218,2985 4231,2998 v1(4244,2998)
SDMMC0_CMD_: D3.5 D3.6 J3.3 R20.2 | length 265.8
  TOP w5: R20.2@4271,3064.72 4271,3090.96 4288.37,3108.33 D3.5@4288.37,3117.78 D3.6@4288.37,3152.22 4288.37,3168.37 4295,3175 4330,3175 4386.61,3231.61 J3.3@4386.61,3262.13
SDMMC0_D0: J2.196 R22.1 | length 3823.1
  TOP w5: J2.196@1686.61,2383.58 1686.61,2349.39 1695.5,2340.5 1701.5,2340.5 1793,2249 1963,2249 v1(1972,2240) ; v1(4445,3027.28) 4477,3027.28 R22.1@4478,3026.28
  BOTTOM w5: v1(1972,2240) 2009,2203 2017.71,2203 2035.71,2185 2225.43,2185 2298.43,2258 2443.71,2258 2523.71,2178 2777,2178 2785,2186 2785,2495 2738,2542 2738,2718 2750,2730 2762,2730 2766.67,2734.67 2767.03,2734.67 2777.77,2745.41 2777.77,2745.77 2785,2753 2785,2789.43 2785,2825.14 2785,2826 2956,2997 2980,2997 2991.5,3008.5 3014.5,3008.5 3031,3025 3595,3025 3665,2955 3955,2955 3996,2996 4073,2996 4121,3044 4241,3044 4283,3002 4416,3002 4441.28,3027.28 v1(4445,3027.28)
SDMMC0_D0_: D4.2 D4.9 J3.7 R22.2 | length 271.8
  TOP w5: R22.2@4478,3061.72 4495,3078.72 4495,3096 4485.32,3105.68 D4.2@4485.32,3117.78 D4.9@4485.32,3152.22 4485.32,3195.32 4498,3208 4548,3208 4560,3220 4560,3261.97 J3.7@4559.84,3262.13
SDMMC0_D1: J2.198 R23.1 | length 3889.1
  TOP w5: J2.198@1666.92,2383.58 1666.92,2348.58 1685.5,2330 1697,2330 1788,2239 1939,2239 1947,2231 v1(1947,2230) ; v1(4444,3000) 4460,3000 4465,3005 4493.72,3005 R23.1@4515,3026.28
  BOTTOM w5: v1(1947,2230) 1957,2220 1975,2220 2002,2193 2013.57,2193 2031.57,2175 2229.57,2175 2302.57,2248 2439.57,2248 2519.57,2168 2788,2168 2795,2175 2795,2500 2749,2546 2749,2706 2763,2720 2773,2720 2795,2742 2795,2793.57 2795,2820.14 2961.86,2987 2985,2987 2996,2998 3019,2998 3036,3015 3590,3015 3660,2945 3960,2945 4001,2986 4078,2986 4126,3034 4236,3034 4278,2992 4422,2992 4430,3000 v1(4444,3000)
SDMMC0_D1_: D4.4 D4.7 J3.8 R23.2 | length 272.5
  TOP w5: R23.2@4515,3061.72 4524.68,3071.4 D4.4@4524.68,3117.78 D4.7@4524.68,3152.22 4524.68,3169.68 4540,3185 4550,3185 4570,3205 4580,3205 4590,3195 4596.59,3195 4603.15,3201.56 J3.8@4603.15,3262.13
SDMMC0_D2: J2.200 R18.1 | length 3859.4
  TOP w5: J2.200@1647.24,2383.58 1647.24,2348.76 1676,2320 1692,2320 1783,2229 1922,2229 1940.5,2210.5 1954.5,2210.5 v1(1965,2200) ; R18.1@4194,3029.28 4198,3025.28 v1(4198,3007)
  BOTTOM w5: v1(1965,2200) 1982,2183 2009.43,2183 2027.43,2165 2233.71,2165 2306.71,2238 2435.43,2238 2515.43,2158 2794,2158 2805,2169 2805,2525 2800,2530 2780,2530 2775,2535 2775,2545 2780,2550 2800,2550 2805,2555 2805,2565 2800,2570 2766,2570 2760,2576 2760,2584 2765,2589 2799,2589 2805,2595 2805,2605 2800,2610 2765,2610 2760,2615 2760,2625 2765,2630 2800,2630 2805,2635 2805,2645 2800,2650 2779,2650 2772.54,2656.46 2772.54,2663.54 2779,2670 2800,2670 2805,2675 2805,2685 2800,2690 2780,2690 2773.54,2696.46 2773.54,2703.54 2780,2710 2800,2710 2805,2715 2805,2797.71 2805,2814.28 2805,2816 2966,2977 2990,2977 3000.5,2987.5 3023.5,2987.5 3041,3005 3585,3005 3655,2935 3965,2935 4006,2976 4083,2976 4131,3024 4186,3024 4198,3012 v1(4198,3007)
SDMMC0_D2_: D3.2 D3.9 J3.1 R18.2 | length 269.3
  TOP w5: R18.2@4194,3064.72 4194,3086.72 4197.28,3090 4211,3090 4229.32,3108.32 D3.2@4229.32,3117.78 D3.9@4229.32,3152.22 4229.32,3194.32 4245,3210 4279,3210 4300,3231 J3.1@4300,3262.13
SDMMC0_D3: J2.202 R19.1 | length 3754.2
  TOP w5: J2.202@1627.55,2383.58 1627.55,2352.45 1670,2310 1687,2310 1778,2219 1917,2219 1930,2206 1930,2201 v1(1939,2192) ; v1(4169,3005) 4173,3005 4193,2985 4193,2933 4200,2926 4223,2926 4229,2932 4229,2949 4218.54,2959.46 4218.54,2966.54 4228,2976 4228,2988.08 4225.67,2990.41 4225.67,3004.33 4220,3010 4220,3015.28 R19.1@4234,3029.28
  BOTTOM w5: v1(1939,2192) 1958,2173 2005.29,2173 2023.29,2155 2237.86,2155 2310.86,2228 2431.28,2228 2511.28,2148 2802,2148 2815,2161 2815,2801.86 2815,2810.14 2971.86,2967 2995,2967 3004.5,2976.5 3027.5,2976.5 3046,2995 3580,2995 3650,2925 3970,2925 4011,2966 4088,2966 4117,2995 4159,2995 v1(4169,3005)
SDMMC0_D3_: D3.4 D3.7 J3.2 R19.2 | length 267.1
  TOP w5: R19.2@4234,3064.72 4234,3086.72 4242.28,3095 4258,3095 4268.68,3105.68 D3.4@4268.68,3117.78 D3.7@4268.68,3152.22 4268.68,3173.68 4290,3195 4316,3195 4343.31,3222.31 J3.2@4343.31,3262.13
SDMMC0_DET_: D4.5 D4.6 J3.9 R24.2 | length 271.4
  TOP w5: R24.2@4550,3061.72 4544.37,3067.35 D4.5@4544.37,3117.78 D4.6@4544.37,3152.22 4544.37,3164.37 4550,3170 4595,3170 4646.46,3221.46 J3.9@4646.46,3262.13
SDMMC0_DET_L: J2.208 R24.1 | length 4104.8
  TOP w5: J2.208@1568.5,2383.58 1568.5,2348.5 1566,2346 1566,2258 1574,2250 1623,2250 1641,2232 1690,2232 1753,2169 1826,2169 1855,2140 v1(1875,2140) ; v1(4515,2995) 4518.72,2995 R24.1@4550,3026.28
  BOTTOM w5: v1(1875,2140) 1883,2132 1883,2122 1894.67,2110.33 1920.98,2110.33 1932.98,2122.33 1973.02,2122.33 1990.35,2105 2259.14,2105 2331.15,2177.01 2343.57,2177.01 ; 2343.58,2177.01 2356,2177.01 2364.28,2177 2411.57,2177 2493.57,2095 2824.14,2095 2831,2101.86 2893,2163.86 2893,2164 2894,2165 2894,2346 2865,2375 2865,2762 3027,2924 3050,2924 3071,2945 3553,2945 3624,2874 3994,2874 4035,2915 4113,2915 4143,2945 4260,2945 4265,2950 4470,2950 4495,2975 4495,2995 4500,3000 4510,3000 v1(4515,2995)
SDMMC2_CLK_M0: J2.27 R187.1 | length 103
  TOP w5: v1(3420,2631) 3428.74,2639.74 J2.27@3428.74,2706.42
  BOTTOM w5: v1(3420,2631) 3420,2612.72 R187.1@3424,2608.72
SDMMC2_CMD_M0: J2.25 R185.2 R186.1 | length 2253.8
  TOP w5: J2.25@3448.42,2706.42 3449.42,2705.42 3449.42,2662.58 3451,2661 v1(3451,2660) ; v1(4065,2062) 4065,1513.78 4076.33,1502.45 4076.33,1493.96 4095.29,1475 4127.29,1475 4160.43,1474.99 4168.71,1475 4464.28,1475 R185.2@4532,1407.28 4532,1369.72 R186.1@4530,1367.72
  BOTTOM w5: v1(3451,2660) 3451,2629 3515,2565 3525,2565 3530,2560 3530,2390 3535,2385 3540,2385 3545,2380 3545,2370 3540,2365 3535,2365 3530,2360 3530,2219.28 3663.28,2086 3972.43,2086 3989,2086 3993,2090 4038,2090 4065,2063 v1(4065,2062)
SDMMC2_D0_M0: J2.17 R180.2 R181.1 | length 2304.7
  TOP w5: J2.17@3527.16,2706.42 3527.16,2660 v1(3532.16,2655) ; v1(3991,2130) 3994,2127 3994,2028.14 4014.14,2008 4020,2002.14 4020,1502.21 4036.33,1485.88 4036.33,1477.39 4079.72,1434 4087.14,1434 4372.28,1434 R180.2@4399.28,1407 4401,1407 4420,1388 4434.72,1388 R181.1@4455,1367.72
  BOTTOM w5: v1(3532.16,2655) 3575,2612.16 3575,2600 3570,2595 3570,2585 3575,2580 3610,2580 3615,2575 3615,2565 3610,2560 3575,2560 3570,2555 3570,2545 3575,2540 3610,2540 3615,2535 3615,2525 3610,2520 3575,2520 3570,2515 3570,2505 3575,2500 3610,2500 3615,2495 3615,2375 3570,2330 3570,2240 3665,2145 3976,2145 v1(3991,2130)
SDMMC2_D1_M0: J2.19 R182.1 | length 2299
  TOP w5: J2.19@3507.48,2706.42 3507.48,2667.52 3513.48,2661.52 v1(3513.48,2634) ; v1(3964,2126) 3984,2106 3984,2024 4010,1998 4010,1498.06 4026.33,1481.74 4026.33,1473.24 4075.57,1424 4091.28,1424 4350,1424 4406.28,1367.72 R182.1@4415,1367.72
  BOTTOM w5: v1(3513.48,2634) 3513.48,2626.24 3521.32,2618.39 3533.39,2618.39 3538.96,2623.96 3546.04,2623.96 3553.96,2616.04 3553.96,2608.96 3543.54,2598.54 3543.54,2591.46 3560,2575 3560,2495 3565,2490 3600,2490 3605,2485 3605,2475 3600,2470 3565,2470 3560,2465 3560,2455 3565,2450 3600,2450 3605,2445 3605,2435 3600,2430 3565,2430 3560,2425 3560,2415 3565,2410 3600,2410 3605,2405 3605,2380 3560,2335 3560,2234.28 3668.28,2126 v1(3964,2126)
SDMMC2_D2_M0: J2.21 R183.1 | length 2332.2
  TOP w5: J2.21@3487.79,2706.42 3487.79,2661 v1(3493.79,2655) ; v1(4095,2086) 4105,2076 4105,2032.14 4086,2013.14 4086,1521.06 4096.33,1510.74 4096.33,1502.24 4103.57,1495 4540,1495 4607,1428 R183.1@4607,1367.72
  BOTTOM w5: v1(3493.79,2655) 3493.79,2626.21 3550,2570 3550,2410 3565,2395 3565,2355 3550,2340 3550,2229.28 3673.28,2106 3980.71,2106 3986.39,2111.67 3998.59,2111.67 4005.92,2119 4062,2119 v1(4095,2086)
SDMMC2_D3_M0: J2.23 R184.1 | length 2330.5
  TOP w5: J2.23@3468.11,2706.42 3468.11,2666.89 3473.65,2661.35 v1(3473.65,2635.65) ; v1(4066,2089) 4095,2060 4095,2037 4076,2018 4076,1516.92 4086.33,1506.59 4086.33,1498.1 4099.43,1485 4131.43,1485 4156.29,1484.99 4164.57,1485 4535,1485 4585,1435 4585,1405 4570,1390 R184.1@4570,1367.72
  BOTTOM w5: v1(3473.65,2635.65) 3473.65,2631.35 3540,2565 3540,2405 3555,2390 3555,2360 3540,2345 3540,2224.28 3668.28,2096 3976.57,2096 3984.85,2096 3990.53,2101.67 4002.74,2101.67 4010.06,2109 4046,2109 v1(4066,2089)
SPI0_CLK: J24.3 R315.6 | length 260.9
  TOP w5: R315.6@5309.69,2290.16 5323.84,2290.16 5339,2275 5355,2275 5405,2325 5405,2400 J24.3@5450,2445
SPI0_CLK_M1: J2.81 R315.3 | length 3242
  TOP w5: J2.81@2897.24,2706.42 2897.24,2741.24 2913,2757 2958.73,2757 v1(2961.19,2759.46) ; v1(5250,2290) 5250.16,2290.16 R315.3@5270.31,2290.16
  BOTTOM w5: v1(2961.19,2759.46) 2961.19,2782.33 3003.86,2825 3025,2825 3095,2895 3528,2895 3599,2824 3752,2824 3770,2806 4000,2806 4059,2865 4305,2865 4340,2900 4510,2900 4640,3030 4722,3030 4757,3065 4959,3065 5059,2965 5059,2816 5070,2805 5070,2640 5165,2545 5165,2465 5260,2370 5260,2300 v1(5250,2290)
SPI0_CS0: J24.4 R315.5 | length 395.8
  TOP w5: R315.5@5309.69,2268.5 5309.69,2255.32 5330,2235 5375,2235 5435,2295 5480,2295 5495,2310 5495,2390 J24.4@5550,2445
SPI0_CS0_M1: J2.83 R315.4 | length 3232.4
  TOP w5: J2.83@2877.55,2706.42 2877.55,2742.55 2902,2767 2942,2767 2969,2794 3098.14,2794 3098.47,2794.33 3099.33,2794.33 3210,2905 3355,2905 3384,2876 3446,2876 v1(3456,2866) ; v1(5225,2250) 5243.5,2268.5 R315.4@5270.31,2268.5
  BOTTOM w5: v1(3456,2866) 3475,2847 3531,2847 3578.5,2799.5 3578.5,2766.5 3599,2746 4030,2746 4089,2805 4336,2805 4371,2840 4600,2840 4710,2950 4890,2950 4910,2930 4935,2930 4955,2910 4955,2626 4976,2605 5045,2605 5125,2525 5125,2445 5200,2370 5200,2275 v1(5225,2250)
SPI0_MISO: J24.2 R315.7 | length 396.3
  TOP w5: R315.7@5309.69,2309.84 5319.69,2309.84 5324.84,2315 5340,2315 5383,2358 5383,2453 5430,2500 5510,2500 5550,2540 J24.2@5550,2545
SPI0_MISO_M1: J2.87 R315.2 | length 3255.1
  TOP w5: J2.87@2838.18,2706.42 2838.18,2739.18 2886,2787 2933.71,2787 2960.71,2814 3089.43,2814 3108,2832.57 3200.43,2925 3365,2925 3394,2896 3652,2896 3735,2813 v1(3735,2795) ; v1(5221,2322) 5221,2321 5232.16,2309.84 R315.2@5270.31,2309.84
  BOTTOM w5: v1(3735,2795) 3744,2786 4010,2786 4069,2845 4315,2845 4350,2880 4520,2880 4645,3005 4710,3005 4735,2980 4935,2980 4975,2940 4975,2650 4993,2632 5048,2632 5145,2535 5145,2455 5240,2360 5240,2341 v1(5221,2322)
SPI0_MOSI: J24.1 R315.8 | length 295.6
  TOP w5: R315.8@5309.69,2331.5 5318.51,2331.5 5325,2325 5335,2325 5373,2363 5373,2458 5450,2535 J24.1@5450,2545
SPI0_MOSI_M1: J2.85 R315.1 | length 3159.9
  TOP w5: J2.85@2857.87,2706.42 2857.87,2739.87 2895,2777 2937.86,2777 2964.86,2804 3094,2804 3205,2915 3360,2915 3389,2886 3463,2886 v1(3483,2866) ; v1(5221,2350) 5239.5,2331.5 R315.1@5270.31,2331.5
  BOTTOM w5: v1(3483,2866) 3492,2857 3536,2857 3589,2804 3589,2775 3608,2756 4025,2756 4084,2815 4331,2815 4366,2850 4595.86,2850 4705.86,2960 4895,2960 4913.65,2941.35 4938.65,2941.35 4965,2915 4965,2644 4991,2618 5047,2618 5135,2530 5135,2450 5221,2364 v1(5221,2350)
SPK_CTL_H_GPIO3_B0: J2.53 R89.1 | length 487.9
  TOP w5: v1(3165,2655) 3172.83,2662.83 J2.53@3172.83,2706.42 ; R89.1@3478,2797.28 3485,2790.28 v1(3485,2768)
  BOTTOM w5: v1(3165,2655) 3165,2675 3258,2768 3270,2768 3278,2776 3398,2776 3408,2786 3480,2786 3485,2781 v1(3485,2768)
SPK_MUTE_H_GPIO3_A7: J2.55 R90.1 | length 518.8
  TOP w5: J2.55@3153.15,2706.42 3153.15,2738.15 3165,2750 3194,2750 v1(3211,2767) ; v1(3527,2775) 3567.72,2775 R90.1@3590,2797.28
  BOTTOM w5: v1(3211,2767) 3212,2767 3234,2789 3261,2789 3268,2796 3388,2796 3398,2806 3494,2806 3525,2775 v1(3527,2775)
SYS_LED_GPIO4_C5: J2.142 R8.1 | length 2215
  TOP w5: J2.142@2296.85,2383.58 2296.85,2348.15 2320,2325 2320,2303 2319.33,2302.33 v1(2319.33,2300) ; v1(3265,3048) 3263,3050 3263,3087.34 3252,3098.34 3252,3145.99 3273.01,3167 3281.29,3167 3310,3167 3315,3172 3315,3294.95 3305,3304.95 R8.1@3305,3325.28
  BOTTOM w5: v1(2319.33,2300) 2319.33,2297.67 2320,2297 2320,2290 2342,2268 2447.85,2268 2527.86,2188 2731,2188 2764,2221 2764,2486 2711,2539 2711,2769 2949,3007 2975,3007 2987,3019 3004,3019 3048,3063 3064,3063 3079,3048 3121,3048 3151,3078 3204,3078 3232,3050 3263,3050 v1(3265,3048)
SYS_RESETN: J2.235 R311.4 | length 7240.6
  TOP w5: v1(1251,2487) 1254,2490 1275,2490 1330,2545 1330,2647 1302.75,2674.25 J2.235@1302.75,2706.42 ; v1(5165,1505) 5178,1505 5188,1495 5193.94,1495 5202.23,1495 5211.3,1485.92 5215.16,1485.92 5281.97,1419.12 5281.97,1409.04 5300.5,1390.5 R311.4@5309.31,1390.5
  BOTTOM w5: v1(1251,2487) 1288,2487 1302,2473 1302,2389 1259,2346 1259,2037.29 1220.5,1998.79 1220.5,1974.5 1215.67,1969.67 1215.67,1421.06 1315,1321.74 1315,1230 1275,1190 1275,1160 1240,1125 1240,1055 1260,1035 1364,1035 1404,995 1404,863 1441,826 1441,808.35 1460.33,789.02 1460.33,756.25 1485,731.57 1485,631 1521,595 1680,595 1776,499 3074,499 3355,780 3355,880 3370,895 3370,960 3475,1065 3490,1065 3515.14,1090.14 3515.14,1101.14 3600.67,1186.67 3600.67,1187.23 3637.77,1224.33 3638.33,1224.33 3682,1268 3798.1,1268 3812.02,1254.08 3899.93,1254.08 3964,1318.14 3964,1418 3994,1448 4594,1448 4613,1429 4685,1429 4712,1402 4779,1402 4852,1475 4853,1475 5072,1694 5110,1694 5115,1689 5115,1555 v1(5165,1505)
TP0_INT: D48.4 D48.7 J15.5 J31.3 R114.2 | length 1937.7
  TOP w5: v1(1414,554) 1414,574.86 1520.14,681 1534,681 1545,692 v1(1545,706)
  BOTTOM w5: J15.5@1027.99,1369.88 1003.88,1369.88 985,1351 985,1080 1060,1005 1105,1005 1170,940 1170,825 1250,745 1300,745 1375,670 1375,565 1386,554 v1(1414,554) ; v1(1545,706) 1517,734 1517,782.14 1516,783.14 1516,784 1500,800 1500,850 1455,895 1455,940 1436,959 1436,991 1445.16,1000.16 J31.3@1445.16,1037.01 1445.16,1075.16 1460,1090 1534,1090 1540.32,1096.32 D48.4@1540.32,1112.78 D48.7@1540.32,1147.22 1540.32,1190.6 R114.2@1547,1197.28
TP0_INT_L_GPIO3_A3: J2.63 R114.1 | length 3663.8
  TOP w5: v1(1819.13,1109.1) 1845.18,1109.1 1852.28,1102 1946,1102 v1(1980,1068) ; v1(3055,2756.7) 3055.7,2756 3056,2756 3074.4,2737.6 J2.63@3074.4,2706.42
  BOTTOM w5: R114.1@1547,1232.72 1547,1332 1559,1344 1574.86,1344 1583.14,1344 1640.82,1401.67 1780.04,1401.67 ; 1780.04,1401.68 1796.61,1401.68 ; 1796.62,1401.67 1802.47,1395.82 1818.33,1379.96 1818.33,1325.74 1808,1315.41 1808,1120.23 v1(1819.13,1109.1) ; v1(1980,1068) 1982,1066 1982,1065 1996,1051 2074,1051 2096,1073 2096,1087 2146,1137 2227,1137 2270,1180 2270,1330 2230,1370 2230,1730 2205,1755 2205,1933.14 2340,2068.14 2340,2101 2356,2117 2384,2117 2466.14,2034.86 2854.86,2034.86 2955,2135 2955,2680 2965,2690 2992,2690 3055,2753 v1(3055,2756.7)
TP0_RST: D48.5 D48.6 J15.4 J31.2 R113.2 | length 1825.6
  TOP w5: v1(1393.5,572.5) 1397.5,572.5 1519,694 v1(1519,700)
  BOTTOM w5: J15.4@1027.99,1350.2 1005.2,1350.2 995,1340 995,1085 1065,1015 1110,1015 1180,945 1180,830 1255,755 1305,755 1385,675 1385,581 v1(1393.5,572.5) ; R113.2@1509,1197.28 1520.63,1185.65 D48.6@1520.63,1147.22 D48.5@1520.63,1112.78 1520.63,1105.63 1515,1100 1450,1100 1425.47,1075.47 J31.2@1425.47,1037.01 1425.47,954.53 1445,935 1445,890 1490,845 1490,795 1507,778 1507,729 1519,717 v1(1519,700)
TP0_RST_L_GPIO3_A4: J2.61 R113.1 | length 3731.7
  TOP w5: v1(3035.35,2775.33) 3036.02,2776 3064,2776 3094.09,2745.91 J2.61@3094.09,2706.42
  BOTTOM w5: R113.1@1509,1232.72 1530,1253.72 1530,1330 1554,1354 1579,1354 1636.67,1411.67 1775.9,1411.67 ; 1775.9,1411.68 1800.75,1411.68 ; 1800.76,1411.67 1812.47,1399.96 1828.33,1384.1 1828.33,1321.59 1819,1312.27 1819,1136 1857,1098 1975.92,1098 2012.92,1061 2065,1061 2086,1082 2086,1092 2141,1147 2222.86,1147 2260,1184.14 2260,1325 2215,1370 2215,1730 2195,1750 2195,1937.29 2330,2072.29 2330,2105.14 2351.86,2127 2389.86,2127 2471.86,2045 2850,2045 2945,2140 2945,2685 2960,2700 2987.86,2700 3035,2747.14 3035,2774.98 v1(3035.35,2775.33)
TP0_SCL: D48.2 D48.9 J15.6 J31.4 R115.2 | length 2129
  TOP w5: v1(1395,535) 1423,535 1433,545 1433,579 1435,581 1435,581.71 1514.29,661 v1(1527,661)
  BOTTOM w5: J15.6@1027.99,1389.57 964.57,1389.57 945,1370 945,1281 975,1251 975,1075 1020,1030 1020,845 1080,785 1195,785 1245,735 1295,735 1365,665 1365,555 1385,535 v1(1395,535) ; v1(1527,661) 1550,661 1565,676 1565,750 1510,805 1510,855 1474,891 1474,991 1464.84,1000.16 J31.4@1464.84,1037.01 1464.84,1069.84 1475,1080 1565,1080 1579.68,1094.68 D48.2@1579.68,1112.78 D48.9@1579.68,1147.22 1579.68,1191.96 R115.2@1585,1197.28
TP0_SDA: D48.1 D48.10 J15.7 J31.5 R116.2 | length 2207.8
  TOP w5: v1(1440,525) 1445,530 1445,577.57 1501.8,634.37 v1(1525.93,634.37)
  BOTTOM w5: J15.7@1027.99,1409.25 969.97,1409.25 935,1374.28 935,1275 965,1245 965,1070 1010,1025 1010,840.86 1075.86,775 1190,775 1240,725 1290,725 1355,660 1355,540 1380,515 1430,515 v1(1440,525) ; v1(1525.93,634.37) 1541.37,634.37 1576,669 1576,754 1520,810 1520,860 1484.53,895.47 J31.5@1484.53,1037.01 1484.53,1059.06 1495.47,1070 1574,1070 1599.37,1095.37 D48.1@1599.37,1112.78 D48.10@1599.37,1147.22 1599.37,1179.37 1617.28,1197.28 R116.2@1623,1197.28
TP1_INT: D34.2 D34.9 J13.5 R95.2 | length 227.6
  TOP w5: J13.5@3876.18,632.01 3876.18,661.18 3920,705 3940,705 3949.68,714.68 D34.9@3949.68,727.78 D34.2@3949.68,762.22 3949.68,816.96 R95.2@3950,817.28
TP1_INT_L_GPIO3_C0: J2.68 R95.1 | length 2226.7
  TOP w5: J2.68@3025.19,2383.58 3025.19,2344.81 3310,2060 3310,2005 3460,1855 3460,1665 3465,1660 3465,1420 3397,1352 3397,1285 v1(3441,1241) ; v1(3396,1200) 3405,1191 3405,1142.86 3531.53,1016.33 3873.67,1016.33 3962,928 3962,877 3950,865 R95.1@3950,852.72
  BOTTOM w5: v1(3396,1200) 3396,1211 3426,1241 v1(3441,1241)
TP1_RST: D34.1 D34.10 J13.4 R94.2 | length 233.9
  TOP w5: J13.4@3895.87,632.01 3895.87,660.87 3930,695 3950,695 3969.37,714.37 D34.10@3969.37,727.78 D34.1@3969.37,762.22 3969.37,781.65 3978.86,791.14 3978.86,811.14 R94.2@3985,817.28
TP1_RST_L_GPIO3_C1: J2.66 R94.1 | length 2234.2
  TOP w5: J2.66@3044.88,2383.58 3044.88,2340.12 3320,2065 3320,2010 3470,1860 3470,1670 3475,1665 3475,1415 3407,1347 3407,1295 3442,1260 3460,1260 v1(3465,1255) ; v1(3424,1205) 3415,1196 3415,1147 3535.67,1026.33 3877.82,1026.33 3878.14,1026 3879,1026 3975,930 3975,875 3985,865 R94.1@3985,852.72
  BOTTOM w5: v1(3424,1205) 3432,1205 3465,1238 v1(3465,1255)
TP1_SCL: D34.4 D34.7 J13.6 R96.2 | length 209.5
  TOP w5: J13.6@3856.5,632.01 3856.5,661.5 3910,715 3910,727.46 D34.7@3910.32,727.78 D34.4@3910.32,762.22 3910.32,812.6 R96.2@3915,817.28
TP1_SDA: D34.5 D34.6 J13.7 R97.2 | length 212
  TOP w5: J13.7@3836.81,632.01 3836.81,661.81 3890.63,715.63 D34.6@3890.63,727.78 D34.5@3890.63,762.22 3890.63,806.65 R97.2@3880,817.28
